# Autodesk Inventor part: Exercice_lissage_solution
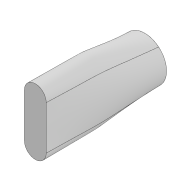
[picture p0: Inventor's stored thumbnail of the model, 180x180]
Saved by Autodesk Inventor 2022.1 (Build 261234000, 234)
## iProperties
Created: 2021-06
Part Number: Exercice_lissage_solution
Material: Générique
Document SubType Name: Modeling
Designer: Fabian
Density: 1 g/cm^3
Appearance: Par défaut
Mass: 16.3044 g
Surface Area: 40.792 cm^2
Volume: 16.3044 cm^3
Author: Fabian
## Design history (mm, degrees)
node "Plan de construction1"
sketch "Esquisse1"
  geometry: C1 r 10 at (0, 0); 1 further point
  constraints: 1 centre point, 1 coincident
  dimensions: "d5" = 20 diameter of C1
sketch "Esquisse2"
  geometry: L1 (0, 10)-(0, -10); L2 (-5, 10)-(-5, -10); L3 (5, -10)-(5, 10); A1 r 5 centre (0, 10) between (5, 10) and (-5, 10); A2 r 5 centre (0, -10) between (-5, -10) and (5, -10); 1 further point
  constraints: 8 end point, 4 point on circle, 4 tangent, 2 centre point, 1 midpoint, 1 parallel, 1 vertical
  dimensions: "d14" = 20 distance of L1.start L1.end; "d15" = 5 radius of A1
sketch "Esquisse3"
  geometry: L1 (10, 0)-(-10, 0) reference; L2 (15, 50)-(10, 50) reference; L3 (-10, 50)-(-15, 50) reference; L4 (0, 0)-(0, 50); L5 (10, 50)-(-10, 50) reference; 4 further points
  constraints: 2 end point, 1 midpoint, 1 symmetric about line, 1 vertical, 6 other
  dimensions: "d16" = 35 distance of point (-17.5, 20) point (17.5, 20); "d17" = 20 vertical distance of L4.start point (17.5, 20)
sketch "Esquisse4"
  geometry: L1 (10, 0)-(-10, 0) reference; L2 (15, 50)-(10, 50) reference; L3 (-10, 50)-(-15, 50) reference; L4 (10, 50)-(-10, 50) reference; L5 (10, 0)-(14.806, 24.029); L6 (15, 25.99)-(15, 50); L7 (0, 0)-(0, 50); L8 (-10, 0)-(-14.806, 24.029); L9 (-15, 25.99)-(-15, 50); A1 r 10 centre (5, 25.99) between (14.806, 24.029) and (15, 25.99); A2 r 10 centre (-5, 25.99) between (-15, 25.99) and (-14.806, 24.029); 4 further points
  constraints: 10 end point, 4 point on circle, 4 point on line, 4 tangent, 2 centre point, 1 equal radius, 1 midpoint, 1 symmetric about line, 1 vertical
  dimensions: "d28" = 25 distance of point (15, 25) L2.start; "d29" = 10 radius of A1
feature "Lissage3" sketch "Esquisse4" dims "d30" = 0, "d31" = 90 deg, "d32" = 0, "d33" = 90 deg, "d34" = 0, "d35" = 90 deg, "d36" = 0, "d37" = 90 deg
node "Solide3"
